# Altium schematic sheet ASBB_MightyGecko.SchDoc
size A4
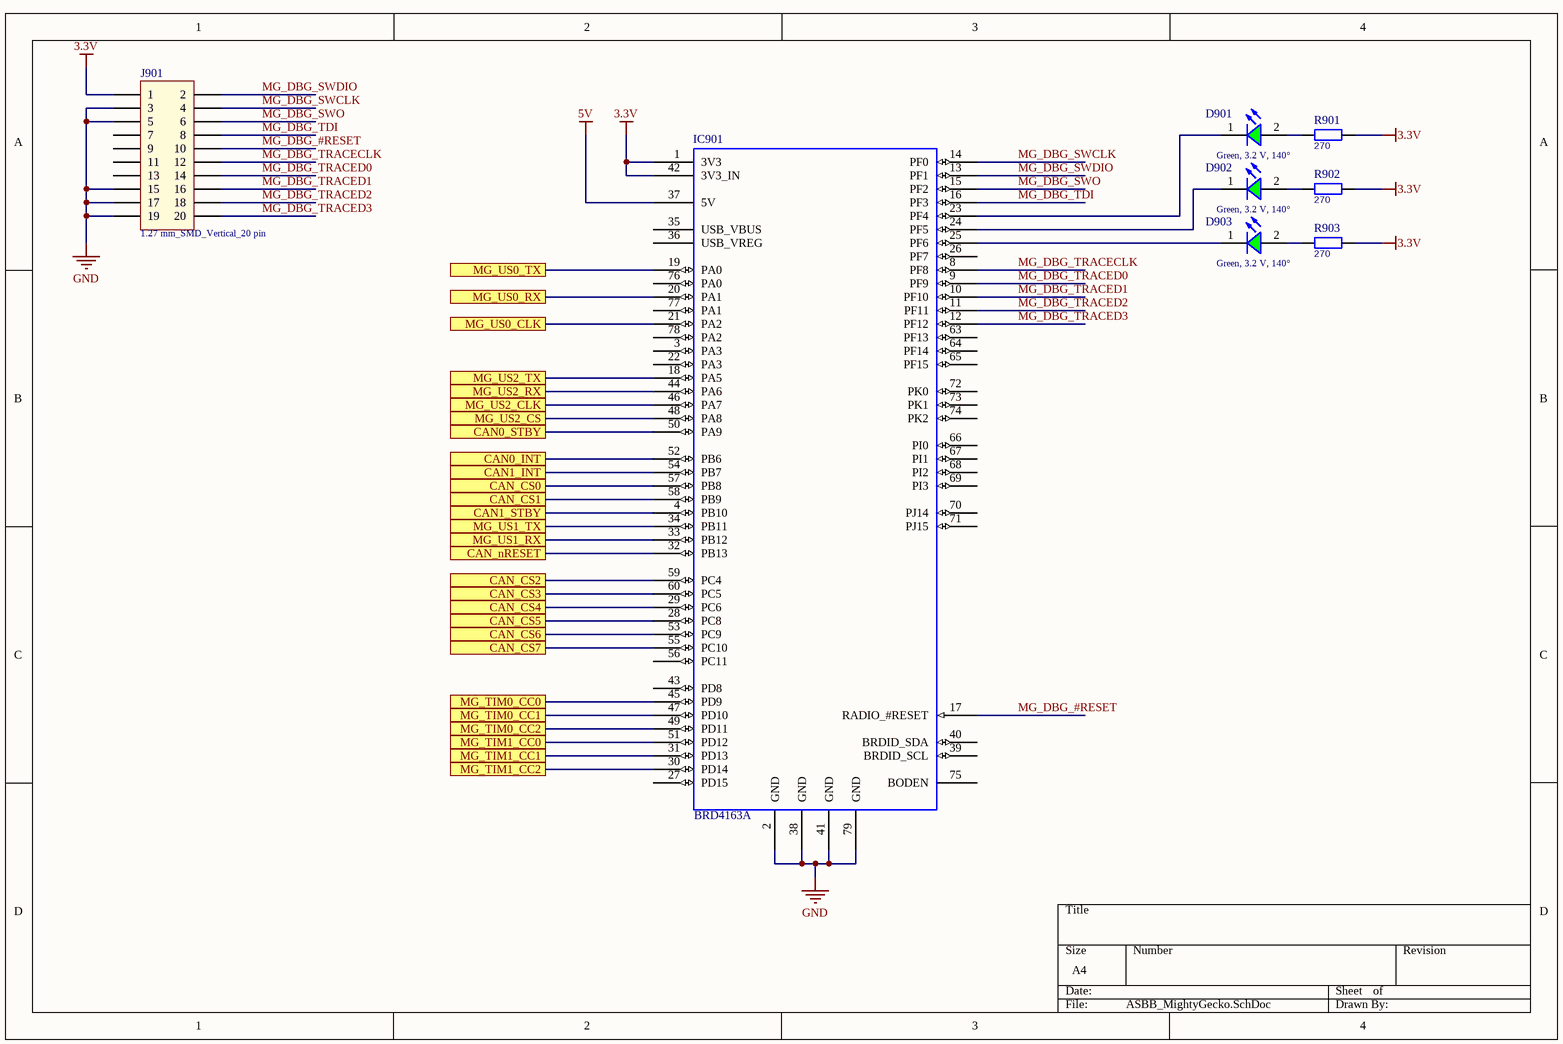
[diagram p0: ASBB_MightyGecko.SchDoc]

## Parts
D901  Green, 3.2 V, 140°  [WL-SMCW_0603]
D902  Green, 3.2 V, 140°  [WL-SMCW_0603]
D903  Green, 3.2 V, 140°  [WL-SMCW_0603]
IC901  BRD4163A  [80-Pin SiLabs Module]
J901  1.27 mm_SMD_Vertical_20 pin  [62102021021]
R901  270  [0603]
R902  270  [0603]
R903  270  [0603]

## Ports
CAN0_INT, CAN0_STBY, CAN1_INT, CAN1_STBY, CAN_CS0, CAN_CS1, CAN_CS2, CAN_CS3, CAN_CS4, CAN_CS5, CAN_CS6, CAN_CS7, CAN_nRESET, MG_TIM0_CC0, MG_TIM0_CC1, MG_TIM0_CC2, MG_TIM1_CC0, MG_TIM1_CC1, MG_TIM1_CC2, MG_US0_CLK, MG_US0_RX, MG_US0_TX, MG_US1_RX, MG_US1_TX, MG_US2_CLK, MG_US2_CS, MG_US2_RX, MG_US2_TX

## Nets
3.3V: IC901.1(3V3) IC901.42(3V3_IN) J901.1 R901.2 R902.2 R903.2
5V: IC901.37(5V)
GND: IC901.2(GND) IC901.38(GND) IC901.41(GND) IC901.79(GND) J901.3 J901.5 J901.15 J901.17 J901.19
CAN0_INT: IC901.52(PB6) ; port CAN0_INT
CAN0_STBY: IC901.50(PA9) ; port CAN0_STBY
CAN1_INT: IC901.54(PB7) ; port CAN1_INT
CAN1_STBY: IC901.4(PB10) ; port CAN1_STBY
CAN_CS0: IC901.57(PB8) ; port CAN_CS0
CAN_CS1: IC901.58(PB9) ; port CAN_CS1
CAN_CS2: IC901.59(PC4) ; port CAN_CS2
CAN_CS3: IC901.60(PC5) ; port CAN_CS3
CAN_CS4: IC901.29(PC6) ; port CAN_CS4
CAN_CS5: IC901.28(PC8) ; port CAN_CS5
CAN_CS6: IC901.53(PC9) ; port CAN_CS6
CAN_CS7: IC901.55(PC10) ; port CAN_CS7
CAN_nRESET: IC901.32(PB13) ; port CAN_nRESET
MG_DBG_#RESET: IC901.17(RADIO_#RESET) J901.10
MG_DBG_SWCLK: IC901.14(PF0) J901.4
MG_DBG_SWDIO: IC901.13(PF1) J901.2
MG_DBG_SWO: IC901.15(PF2) J901.6
MG_DBG_TDI: IC901.16(PF3) J901.8
MG_DBG_TRACECLK: IC901.8(PF8) J901.12
MG_DBG_TRACED0: IC901.9(PF9) J901.14
MG_DBG_TRACED1: IC901.10(PF10) J901.16
MG_DBG_TRACED2: IC901.11(PF11) J901.18
MG_DBG_TRACED3: IC901.12(PF12) J901.20
MG_TIM0_CC0: IC901.45(PD9) ; port MG_TIM0_CC0
MG_TIM0_CC1: IC901.47(PD10) ; port MG_TIM0_CC1
MG_TIM0_CC2: IC901.49(PD11) ; port MG_TIM0_CC2
MG_TIM1_CC0: IC901.51(PD12) ; port MG_TIM1_CC0
MG_TIM1_CC1: IC901.31(PD13) ; port MG_TIM1_CC1
MG_TIM1_CC2: IC901.30(PD14) ; port MG_TIM1_CC2
MG_US0_CLK: IC901.21(PA2) ; port MG_US0_CLK
MG_US0_RX: IC901.20(PA1) ; port MG_US0_RX
MG_US0_TX: IC901.19(PA0) ; port MG_US0_TX
MG_US1_RX: IC901.33(PB12) ; port MG_US1_RX
MG_US1_TX: IC901.34(PB11) ; port MG_US1_TX
MG_US2_CLK: IC901.46(PA7) ; port MG_US2_CLK
MG_US2_CS: IC901.48(PA8) ; port MG_US2_CS
MG_US2_RX: IC901.44(PA6) ; port MG_US2_RX
MG_US2_TX: IC901.18(PA5) ; port MG_US2_TX
NetD901_1: D901.1(K) IC901.23(PF4)
NetD901_2: D901.2(A) R901.1
NetD902_1: D902.1(K) IC901.24(PF5)
NetD902_2: D902.2(A) R902.1
NetD903_1: D903.1(K) IC901.25(PF6)
NetD903_2: D903.2(A) R903.1

Not connected (* = marked no-connect by the designer): IC901 3(PA3) 5(NC) 6(NC) 7(NC) 22(PA3) 26(PF7) 27(PD15) 35(USB_VBUS) 36(USB_VREG) 39(BRDID_SCL) 40(BRDID_SDA) 43(PD8) 56(PC11) 61(NC) 62(NC) 63(PF13) 64(PF14) 65(PF15) 66(PI0) 67(PI1) 68(PI2) 69(PI3) 70(PJ14) 71(PJ15) 72(PK0) 73(PK1) 74(PK2) 75(BODEN) 76(PA0) 77(PA1) 78(PA2) 80(NC); J901 7 9 11 13

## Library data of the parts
D901-D903 = 150060GS75000: WL-SMCW SMD Mono-color Chip LED Waterclear, size 0603, Green, 3.2 V, 140°; Forward Voltage: 3.2 V; Peak Wavelength: 515 nm; Dominant Wavelength: 525 nm; Luminous Intensity: 430 mcd
IC901 = SLWRB4163A
J901 = 62102021021: Pin Header WR-PHD, pitch 1.27 mm, SMD, Vertical, dual row, 20 pin; Rated Current: 1 A; Pin Number: 20; Pitch: 1.27 mm; Working Voltage: 100 VAC; Contact Resistance: 20 mOhm; Insulation Resistance: >1000 MOhm
R901-R903 = Resistor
